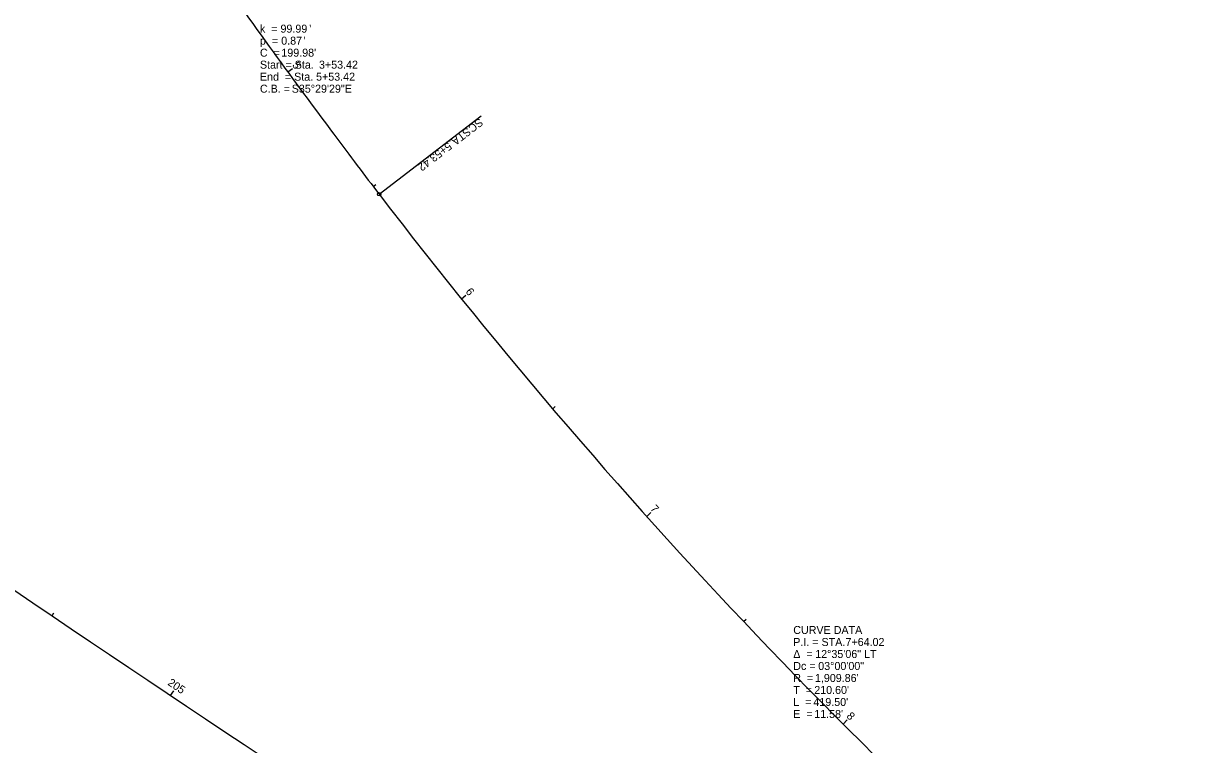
# Model space of a CAD drawing. Extents: x 1323137 to 1326838, y 458936 to 461644.
# Drawn here: x 1325549.7 to 1325963.8, y 459709.4 to 459961.6 of the extents above; entities that cross this region are included whole.
import ezdxf

# ---------------------------------------------------------------- set-up
doc = ezdxf.new("R2010")
doc.units = 0
for name, color, linetype in [('CM_Corridor_Range_Final', 7, 'Continuous'), ('Default', 7, 'Continuous'), ('MD_P_ACB_B', 7, 'Continuous'), ('MD_P_AGB_T', 7, 'Continuous'), ('SG_P_Conduit', 7, 'Continuous'), ('SG_P_Mast_Arm', 7, 'Continuous'), ('SN_P_Signs', 7, 'Continuous'), ('SN_X_Public', 7, 'Continuous')]:
    doc.layers.add(name, color=color, linetype=linetype)

msp = doc.modelspace()

# ---------------------------------------------------------------- linework, layer by layer
at = {"layer": 'CM_Corridor_Range_Final'}
for p, q in [((1325559.67, 459754.35), (1325560.34, 459755.34)), ((1325601.16, 459726.45), (1325602.27, 459728.11))]:
    msp.add_line(p, q, dxfattribs=at)
at = {"layer": 'Default'}
for centre, radius, start, end in [((1332431.06, 469929.07), 12277.67, 232.043309, 236.873031), ((1327189.47, 461064.32), 1909.86, 217.49136, 230.07643)]:
    msp.add_arc(centre, radius, start, end, dxfattribs=at)
msp.add_open_spline([(1325558, 460064.72), (1325562.72, 460057.86), (1325572.16, 460044.12), (1325591.08, 460016.68), (1325614.9, 459982.49), (1325639.17, 459948.61), (1325658.98, 459921.81), (1325669.03, 459908.51), (1325674.1, 459901.9)], degree=3, dxfattribs=at)
at = {"layer": 'MD_P_ACB_B'}
msp.add_line((1325674.1, 459901.9), (1325709.81, 459929.29), dxfattribs=at)
msp.add_circle((1325674.1, 459901.9), 0.6, dxfattribs=at)
at = {"layer": 'SG_P_Conduit'}
msp.add_arc((1327189.47, 461064.32), 1909.86, 217.49136, 230.07643, dxfattribs=at)
msp.add_open_spline([(1325558, 460064.72), (1325562.72, 460057.86), (1325572.16, 460044.12), (1325591.08, 460016.68), (1325614.9, 459982.49), (1325639.17, 459948.61), (1325658.98, 459921.81), (1325669.03, 459908.51), (1325674.1, 459901.9)], degree=3, dxfattribs=at)
at = {"layer": 'SG_P_Mast_Arm'}
for p, q in [((1325642.13, 459944.7), (1325643.75, 459945.88)), ((1325672.03, 459904.62), (1325672.98, 459905.35)), ((1325702.9, 459865.29), (1325704.46, 459866.55)), ((1325734.8, 459826.79), (1325735.71, 459827.57)), ((1325767.69, 459789.14), (1325769.18, 459790.47)), ((1325801.56, 459752.35), (1325802.43, 459753.18)), ((1325836.38, 459716.47), (1325837.8, 459717.88))]:
    msp.add_line(p, q, dxfattribs=at)
at = {"layer": 'SN_P_Signs'}
for centre, radius, start, end in [((1332431.06, 469929.07), 12277.67, 232.043309, 236.873031), ((1327189.47, 461064.32), 1909.86, 217.49136, 230.07643)]:
    msp.add_arc(centre, radius, start, end, dxfattribs=at)
msp.add_open_spline([(1325558, 460064.72), (1325562.72, 460057.86), (1325572.16, 460044.12), (1325591.08, 460016.68), (1325614.9, 459982.49), (1325639.17, 459948.61), (1325658.98, 459921.81), (1325669.03, 459908.51), (1325674.1, 459901.9)], degree=3, dxfattribs=at)
at = {"layer": 'SN_X_Public'}
msp.add_line((1325601.16, 459726.45), (1325602.27, 459728.11), dxfattribs=at)

# ---------------------------------------------------------------- texts
at = {"layer": 'CM_Corridor_Range_Final'}
msp.add_text('205', height=2.8, rotation=326.2006, dxfattribs=at).set_placement((1325599.88, 459730.31))
at = {"layer": 'MD_P_ACB_B'}
for s, p in [('SC', (1325709.08, 459928.68)), (' STA. ', (1325705.67, 459926.06)), ('5+53.42', (1325698.17, 459920.31))]:
    msp.add_text(s, height=2.8, rotation=217.4914, dxfattribs=at).set_placement(p)
at = {"layer": 'MD_P_AGB_T'}
for s, p in [('k  = ', (1325632.39, 459958.45)), ('99.99', (1325639.58, 459958.45)), ("'", (1325649.64, 459958.45)), ('p  = ', (1325632.39, 459954.25)), ('0.87', (1325639.84, 459954.25)), ("'", (1325647.66, 459954.25)), ('C  = ', (1325632.39, 459950.05)), ("199.98'", (1325639.88, 459950.05)), ('Start = Sta. ', (1325632.39, 459945.85)), ('3+53.42', (1325653.04, 459945.85)), ('End  = Sta. ', (1325632.39, 459941.65)), ('5+53.42', (1325652.02, 459941.65)), ('C.B. = ', (1325632.39, 459937.45)), ('S35°29\'29"E', (1325643.51, 459937.45)), ('CURVE DATA', (1325818.95, 459747.98)), ('P.I. = STA. ', (1325818.95, 459743.78)), ('7+64.02', (1325837.22, 459743.78)), ('Δ  = ', (1325818.95, 459739.58)), ('12°35\'06" LT', (1325826.63, 459739.58)), ('Dc = ', (1325818.95, 459735.38)), ('03°00\'00"', (1325827.69, 459735.38)), ('R  = ', (1325818.95, 459731.18)), ("1,909.86'", (1325826.53, 459731.18)), ('T  = ', (1325818.95, 459726.98)), ("210.60'", (1325826.29, 459726.98)), ('L  = ', (1325818.95, 459722.78)), ("419.50'", (1325825.99, 459722.78)), ('E  = ', (1325818.95, 459718.58)), ("11.58'", (1325826.29, 459718.58))]:
    msp.add_text(s, height=2.8, dxfattribs=at).set_placement(p)
at = {"layer": 'SG_P_Mast_Arm'}
for s, rotation, p in [('5', 306.1028, (1325643.52, 459947.04)), ('6', 308.8888, (1325704.14, 459867.74)), ('7', 311.8888, (1325768.76, 459791.68)), ('8', 314.8888, (1325837.37, 459719.02))]:
    msp.add_text(s, height=2.8, rotation=rotation, dxfattribs=at).set_placement(p)
at = {"layer": 'SN_X_Public'}
msp.add_text('205', height=2.8, rotation=326.2006, dxfattribs=at).set_placement((1325599.88, 459730.31))

doc.saveas('drawing.dxf')
